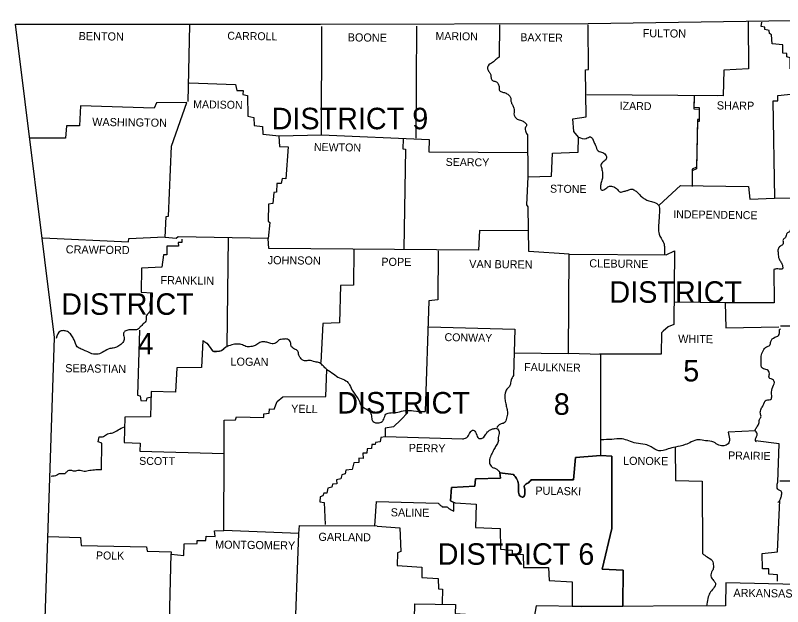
# Model space of a CAD drawing. Extents: x 1096785 to 1382432, y 216169 to 341661.
# Drawn here: x 1206233 to 1214365, y 286518 to 292788 of the extents above; entities that cross this region are included whole.
import ezdxf

# ---------------------------------------------------------------- set-up
doc = ezdxf.new("R2010")
doc.units = 0
for name, color, linetype in [('1', 7, 'Continuous'), ('21', 7, 'Continuous'), ('3', 7, 'Continuous')]:
    doc.layers.add(name, color=color, linetype=linetype)

msp = doc.modelspace()

# ---------------------------------------------------------------- linework, layer by layer
at = {"layer": '1'}
for p, q in [((1214341.4, 289493.9), (1214579.4, 289493.9)), ((1210893.4, 287619.9), (1210879.4, 287621.9)), ((1210879.4, 287621.9), (1210893.4, 287619.9)), ((1210067.4, 287371.9), (1210043.4, 287375.9)), ((1210757.4, 286553.9), (1210757.2, 286543.8)), ((1212133.4, 286521.9), (1212133.4, 286521.5)), ((1212133.4, 286521.9), (1212133.4, 286521.5)), ((1212133.4, 286521.5), (1212229.4, 286519.9)), ((1212229.4, 286519.9), (1212671.4, 286521.6)), ((1212671.4, 286535.9), (1212671.4, 286521.6)), ((1212671.4, 286521.6), (1212671.4, 286535.9))]:
    msp.add_line(p, q, dxfattribs=at)
for points in [[(1206233.4, 292695.9), (1209467.4, 292693.9), (1212305.4, 292699.9), (1215653.4, 292751.9), (1217205.4, 292787.9)], [(1206467.4, 283945.9), (1206647.4, 289371.9), (1206233.4, 292695.9)], [(1208079.4, 292683.9), (1208061.4, 291873.9)], [(1208075.4, 292071.9), (1208567.4, 292055.9), (1208579.4, 291991.9), (1208647.4, 291989.9), (1208645.4, 291949.9), (1208693.4, 291937.9), (1208697.4, 291719.9), (1208759.4, 291705.9), (1208763.4, 291619.9), (1208851.4, 291607.9), (1208855.4, 291527.9), (1209029.4, 291509.9), (1209477.4, 291519.9), (1209481.4, 292669.9)], [(1210483.4, 292673.9), (1210477.4, 291485.9)], [(1211363.4, 292687.9), (1211359.4, 292345.9)], [(1211699.4, 287861.9), (1212149.4, 287863.9), (1212169.4, 288099.9), (1212437.4, 288119.9), (1212437.4, 289191.9), (1212097.4, 289201.9), (1212103.4, 290255.9), (1211675.4, 290283.9), (1211669.4, 290755.9), (1211655.4, 290779.9), (1211667.4, 291075.9), (1211915.4, 291083.9), (1211925.4, 291327.9), (1212197.4, 291337.9), (1212201.4, 291495.9), (1212153.4, 291557.9), (1212141.4, 291691.9), (1212281.4, 291711.9), (1212275.4, 292209.9), (1212309.4, 292211.9), (1212305.4, 292687.9)], [(1213999.4, 292717.9), (1214003.4, 292221.9), (1213743.4, 292207.9), (1213735.4, 291935.9), (1212289.4, 291943.9)], [(1214565.4, 289481.9), (1214575.4, 289211.9), (1215101.4, 289225.9), (1215087.4, 290829.9), (1214281.4, 290847.9), (1214263.4, 291879.9), (1214315.4, 291881.9), (1214313.4, 291937.9), (1214483.4, 291953.9), (1214475.4, 292215.9), (1214443.4, 292221.9), (1214445.4, 292337.9), (1214409.4, 292347.9), (1214409.4, 292381.9), (1214367.4, 292387.9), (1214367.4, 292473.9), (1214253.4, 292485.9), (1214247.4, 292581.9), (1214225.4, 292595.9), (1214221.4, 292627.9), (1214175.4, 292637.9), (1214177.4, 292661.9), (1214137.4, 292667.9), (1214143.4, 292715.9)], [(1208921.4, 290315.9), (1208911.4, 290421.9), (1207957.4, 290439.9), (1207939.4, 290421.9), (1207821.4, 290431.9), (1207833.4, 290655.9), (1207857.4, 290657.9), (1207889.4, 291399.9), (1208051.4, 291863.9), (1207729.4, 291861.9), (1207705.4, 291801.9), (1206925.4, 291829.9), (1206913.4, 291615.9), (1206775.4, 291615.9), (1206765.4, 291483.9), (1206391.4, 291485.9)], [(1213427.4, 291929.9), (1213423.4, 291813.9), (1213479.4, 291809.9), (1213481.4, 291681.9), (1213461.4, 291681.9), (1213453.4, 291177.9), (1213407.4, 291157.9), (1213407.4, 290989.9)], [(1213427.4, 291911.9), (1213423.4, 291795.9), (1213479.4, 291791.9), (1213481.4, 291663.9), (1213461.4, 291663.9), (1213453.4, 291159.9), (1213407.4, 291139.9), (1213407.4, 290971.9)], [(1213677.4, 291925.9), (1213679.4, 291927.9)], [(1209025.4, 291505.9), (1209033.4, 291397.9), (1209125.4, 291391.9), (1209101.4, 291055.9), (1209059.4, 291057.9), (1209051.4, 291003.9), (1209003.4, 291003.9), (1209001.4, 290911.9), (1208971.4, 290909.9), (1208961.4, 290791.9), (1208917.4, 290785.9), (1208911.4, 290605.9), (1208931.4, 290591.9), (1208911.4, 290421.9)], [(1209477.4, 291519.9), (1210617.4, 291471.9), (1210615.4, 291341.9), (1211661.4, 291333.9)], [(1210343.4, 291477.9), (1210341.4, 291373.9), (1210367.4, 291367.9), (1210351.4, 290311.9)], [(1211667.4, 291075.9), (1211665.4, 291525.9)], [(1213055.4, 290775.9), (1213283.4, 290981.9), (1214003.4, 290971.9), (1214017.4, 290837.9), (1214279.4, 290847.9)], [(1211667.4, 290501.9), (1211151.4, 290507.9), (1211141.4, 290297.9), (1208921.4, 290315.9)], [(1206523.4, 290429.9), (1207433.4, 290387.9), (1207437.4, 290419.9), (1207817.4, 290437.9)], [(1207997.4, 290413.9), (1207997.4, 290377.9), (1207959.4, 290377.9), (1207961.4, 290341.9), (1207839.4, 290339.9), (1207837.4, 290249.9), (1207803.4, 290249.9), (1207785.4, 290115.9), (1207569.4, 290105.9), (1207567.4, 289851.9), (1207683.4, 289843.9)], [(1208219.4, 289339.9), (1208263.4, 289311.9), (1208327.4, 289227.9), (1208377.4, 289225.9), (1208417.4, 289233.9), (1208463.4, 289273.9), (1208477.4, 289275.9), (1208491.4, 290429.9)], [(1208477.4, 289275.9), (1208491.4, 290429.9)], [(1209819.4, 290299.9), (1209817.4, 289925.9), (1209679.4, 289923.9), (1209667.4, 289525.9), (1209491.4, 289519.9), (1209471.4, 289107.9)], [(1210715.4, 290289.9), (1210711.4, 289769.9), (1210615.4, 289761.9), (1210577.4, 288585.9)], [(1212103.4, 290255.9), (1213131.4, 290249.9), (1213219.4, 290291.9), (1213213.4, 289509.9), (1213153.4, 289483.9), (1213099.4, 289437.9), (1213081.4, 289419.9), (1213079.4, 289195.9), (1212425.4, 289195.9)], [(1214271.4, 290091.9), (1214275.4, 289739.9), (1213755.4, 289737.9), (1213221.4, 289747.9)], [(1213755.4, 289737.9), (1213763.4, 289475.9), (1214325.4, 289485.9)], [(1207547.4, 289447.9), (1207527.4, 288759.9), (1207557.4, 288751.9), (1207563.4, 288703.9), (1207623.4, 288699.9), (1207629.4, 288733.9), (1207677.4, 288741.9)], [(1210611.4, 289483.9), (1211525.4, 289461.9), (1211513.4, 288967.9)], [(1214341.4, 289459.9), (1214331.4, 289457.9)], [(1208219.4, 289339.9), (1208205.4, 289053.9), (1207945.4, 289051.9), (1207931.4, 288791.9), (1207673.4, 288797.9), (1207665.4, 288529.9), (1207395.4, 288527.9), (1207387.4, 288259.9), (1207557.4, 288249.9), (1207551.4, 288167.9), (1208446.2, 288143.1)], [(1211515.4, 289209.9), (1212097.4, 289201.9)], [(1215101.4, 289225.9), (1215131.4, 288129.9), (1214655.4, 288127.9), (1214653.4, 288083.9), (1214515.4, 288075.9), (1214503.4, 287847.9), (1214335.4, 287847.9)], [(1208446.2, 288143.1), (1208447.4, 288493.9), (1208567.4, 288497.9), (1208577.4, 288529.9), (1208867.4, 288521.9), (1208865.4, 288563.9), (1208923.4, 288569.9), (1208925.4, 288615.9), (1208975.4, 288611.9), (1209009.4, 288691.9), (1209069.4, 288743.9), (1209525.4, 288745.9), (1209533.4, 289033.9)], [(1210391.4, 288577.9), (1210319.4, 288499.9), (1210241.4, 288425.9), (1210151.4, 288411.9), (1210151.4, 288317.9), (1210107.4, 288311.9), (1210099.4, 288263.9), (1210049.4, 288259.9), (1210045.4, 288237.9), (1210011.4, 288235.9), (1210009.4, 288193.9), (1209961.4, 288191.9), (1209957.4, 288143.9), (1209917.4, 288143.9), (1209919.4, 288087.9), (1209875.4, 288091.9), (1209873.4, 288047.9), (1209819.4, 288043.9), (1209803.4, 287971.9), (1209735.4, 287965.9), (1209729.4, 287925.9), (1209693.4, 287915.9), (1209683.4, 287873.9), (1209637.4, 287863.9), (1209641.4, 287821.9), (1209595.4, 287817.9), (1209587.4, 287785.9), (1209545.4, 287773.9), (1209535.4, 287719.9), (1209503.4, 287721.9), (1209493.4, 287693.9), (1209463.4, 287683.9), (1209461.4, 287629.9), (1209507.4, 287621.9), (1209515.4, 287389.9)], [(1214077.4, 288381.9), (1213787.4, 288367.9)], [(1207145.4, 287969.9), (1207151.4, 288251.9), (1207111.4, 288263.9), (1207123.4, 288317.9)], [(1210977.4, 288293.9), (1210153.4, 288319.9)], [(1214313.4, 287837.9), (1214327.4, 288245.9), (1214077.4, 288277.9)], [(1213227.4, 288211.9), (1213231.4, 287853.9), (1213513.4, 287847.9), (1213515.4, 287079.9)], [(1206553.4, 285611.9), (1207099.4, 285587.9), (1207101.4, 285843.9), (1207073.4, 285863.9), (1207091.4, 286091.9), (1207861.4, 286089.9), (1207883.4, 287073.9), (1208019.4, 287061.9), (1208021.4, 287183.9), (1208161.4, 287187.9), (1208159.4, 287219.9), (1208253.4, 287219.9), (1208255.4, 287263.9), (1208351.4, 287261.9), (1208343.4, 287321.9), (1208443.4, 287323.9), (1208446.2, 288143.1)], [(1212437.4, 288119.9), (1212169.4, 288099.9), (1212149.4, 287863.9), (1211699.4, 287861.9)], [(1212437.4, 288119.9), (1212553.4, 288111.9), (1212555.4, 287347.9), (1212451.4, 286913.9), (1212673.4, 286903.9), (1212671.4, 286535.9)], [(1212671.4, 286535.9), (1212673.4, 286903.9), (1212451.4, 286913.9), (1212555.4, 287347.9), (1212553.4, 288111.9), (1212437.4, 288119.9)], [(1210879.4, 287529.9), (1210879.4, 287621.9), (1210843.4, 287639.9), (1210857.4, 287779.9), (1211103.4, 287793.9), (1211111.4, 287871.9), (1211373.4, 287881.9), (1211367.4, 287935.9), (1211511.4, 287919.9)], [(1211511.4, 287919.9), (1211367.4, 287935.9), (1211373.4, 287881.9), (1211111.4, 287871.9), (1211103.4, 287793.9), (1210857.4, 287779.9), (1210843.4, 287639.9), (1210879.4, 287621.9)], [(1212139.4, 287865.9), (1212149.4, 287875.9)], [(1209239.4, 287293.9), (1209243.4, 287379.9), (1210043.4, 287375.9), (1210061.4, 287633.9), (1210715.4, 287613.9)], [(1214311.4, 286787.9), (1214309.4, 286853.9), (1214219.4, 286863.9), (1214217.4, 286919.9), (1214151.4, 286917.9), (1214147.4, 287079.9), (1214311.4, 287097.9), (1214335.4, 287645.9)], [(1210893.4, 287619.9), (1211117.4, 287605.9), (1211109.4, 287355.9), (1211371.4, 287345.9), (1211375.4, 287127.9), (1211499.4, 287117.9), (1211499.4, 287079.9), (1211615.4, 287071.9), (1211619.4, 286931.9), (1211883.4, 286931.9), (1211891.4, 286793.9), (1212135.4, 286781.9), (1212133.4, 286521.9)], [(1210893.4, 287619.9), (1211117.4, 287605.9), (1211109.4, 287355.9), (1211371.4, 287345.9), (1211375.4, 287127.9), (1211499.4, 287117.9), (1211499.4, 287079.9), (1211615.4, 287071.9), (1211619.4, 286931.9), (1211883.4, 286931.9), (1211891.4, 286793.9), (1212135.4, 286781.9), (1212133.4, 286521.9)], [(1210067.4, 287371.9), (1210309.4, 287353.9), (1210317.4, 287101.9), (1210283.4, 287089.9), (1210279.4, 286955.9), (1210541.4, 286937.9), (1210541.4, 286827.9), (1210715.4, 286817.9), (1210717.4, 286707.9), (1210759.4, 286701.9), (1210757.4, 286553.9)], [(1206577.4, 287261.9), (1206923.4, 287249.9), (1206931.4, 287165.9), (1207623.4, 287151.9), (1207631.4, 287107.9), (1207883.4, 287099.9), (1207881.4, 287061.9)], [(1209193.4, 286047.9), (1209239.4, 287293.9)], [(1214519.4, 286751.9), (1213763.4, 286771.9), (1213759.4, 286525.9), (1212229.4, 286519.9)], [(1209207.4, 286213.9), (1210351.4, 286197.9), (1210373.4, 286387.9), (1210463.4, 286387.9), (1210465.4, 286547.9), (1210897.4, 286541.9), (1210893.4, 286445.9), (1211005.4, 286437.9), (1211005.4, 286261.9), (1211077.4, 286255.9)], [(1212229.4, 286519.9), (1211751.4, 286527.9), (1211733.4, 286405.9), (1211267.4, 286391.9), (1211263.4, 286351.9), (1211197.4, 286339.9), (1211189.4, 286271.9), (1211077.4, 286255.9)]]:
    msp.add_lwpolyline(points, dxfattribs=at)
for points in [[(1211359.4, 292345.9), (1211323.4, 292315.9), (1211291.4, 292287.9), (1211243.4, 292253.9), (1211237.4, 292221.9), (1211253.4, 292189.9), (1211269.4, 292163.9), (1211275.4, 292127.9), (1211289.4, 292097.9), (1211323.4, 292085.9), (1211351.4, 292059.9), (1211361.4, 292023.9), (1211365.4, 291989.9), (1211397.4, 291973.9), (1211433.4, 291961.9), (1211467.4, 291937.9), (1211483.4, 291907.9), (1211487.4, 291869.9), (1211501.4, 291839.9), (1211517.4, 291803.9), (1211521.4, 291773.9), (1211517.4, 291743.9), (1211525.4, 291715.9), (1211551.4, 291687.9), (1211597.4, 291673.9), (1211629.4, 291653.9), (1211651.4, 291625.9), (1211637.4, 291591.9), (1211639.4, 291561.9), (1211657.4, 291525.9)], [(1212201.4, 291495.9), (1212281.4, 291481.9), (1212329.4, 291499.9), (1212363.4, 291447.9), (1212381.4, 291407.9), (1212411.4, 291349.9), (1212459.4, 291331.9), (1212495.4, 291299.9), (1212495.4, 291265.9), (1212463.4, 291233.9), (1212439.4, 291201.9), (1212447.4, 291163.9), (1212455.4, 291111.9), (1212455.4, 291061.9), (1212443.4, 291015.9), (1212433.4, 290973.9), (1212443.4, 290937.9), (1212481.4, 290943.9), (1212521.4, 290973.9), (1212563.4, 290973.9), (1212603.4, 290951.9), (1212645.4, 290913.9), (1212687.4, 290921.9), (1212721.4, 290931.9), (1212769.4, 290945.9), (1212803.4, 290927.9), (1212833.4, 290903.9), (1212869.4, 290865.9), (1212903.4, 290841.9), (1212947.4, 290819.9), (1213001.4, 290805.9), (1213051.4, 290771.9), (1213059.4, 290713.9), (1213057.4, 290663.9), (1213053.4, 290601.9), (1213049.4, 290533.9), (1213055.4, 290467.9), (1213077.4, 290423.9), (1213105.4, 290371.9), (1213113.4, 290323.9), (1213111.4, 290247.9)], [(1214629.4, 290811.9), (1214605.4, 290749.9), (1214577.4, 290689.9), (1214559.4, 290637.9), (1214521.4, 290607.9), (1214509.4, 290579.9), (1214475.4, 290567.9), (1214449.4, 290527.9), (1214437.4, 290491.9), (1214409.4, 290475.9), (1214395.4, 290431.9), (1214369.4, 290407.9), (1214371.4, 290367.9), (1214341.4, 290339.9), (1214317.4, 290307.9), (1214317.4, 290263.9), (1214327.4, 290205.9), (1214347.4, 290171.9), (1214365.4, 290127.9), (1214363.4, 290099.9), (1214313.4, 290099.9), (1214271.4, 290091.9)], [(1207683.4, 289843.9), (1207683.4, 289801.9), (1207667.4, 289757.9), (1207657.4, 289719.9), (1207663.4, 289669.9), (1207645.4, 289629.9), (1207619.4, 289597.9), (1207619.4, 289557.9), (1207589.4, 289515.9), (1207557.4, 289483.9), (1207529.4, 289457.9), (1207479.4, 289453.9), (1207437.4, 289451.9), (1207395.4, 289437.9), (1207379.4, 289407.9), (1207387.4, 289361.9), (1207371.4, 289317.9), (1207329.4, 289283.9), (1207283.4, 289261.9), (1207235.4, 289253.9), (1207169.4, 289221.9), (1207109.4, 289195.9), (1207045.4, 289199.9), (1206985.4, 289225.9), (1206931.4, 289249.9), (1206889.4, 289273.9), (1206855.4, 289347.9), (1206833.4, 289387.9), (1206795.4, 289427.9), (1206749.4, 289443.9), (1206711.4, 289439.9), (1206665.4, 289361.9)], [(1214087.4, 288263.9), (1214077.4, 288277.9), (1214089.4, 288321.9), (1214095.4, 288349.9), (1214075.4, 288389.9), (1214093.4, 288423.9), (1214113.4, 288459.9), (1214119.4, 288501.9), (1214135.4, 288529.9), (1214129.4, 288565.9), (1214137.4, 288615.9), (1214159.4, 288653.9), (1214191.4, 288707.9), (1214245.4, 288721.9), (1214249.4, 288743.9), (1214247.4, 288793.9), (1214269.4, 288867.9), (1214277.4, 288893.9), (1214269.4, 288917.9), (1214221.4, 288945.9), (1214225.4, 288987.9), (1214201.4, 289027.9), (1214151.4, 289045.9), (1214137.4, 289113.9), (1214137.4, 289173.9), (1214159.4, 289231.9), (1214193.4, 289273.9), (1214229.4, 289289.9), (1214239.4, 289329.9), (1214283.4, 289373.9), (1214321.4, 289391.9), (1214331.4, 289457.9)], [(1208219.4, 289339.9), (1208263.4, 289311.9), (1208297.4, 289265.9), (1208327.4, 289227.9), (1208377.4, 289225.9), (1208417.4, 289233.9), (1208463.4, 289273.9)], [(1209533.4, 289033.9), (1209495.4, 289069.9), (1209455.4, 289103.9), (1209411.4, 289113.9), (1209343.4, 289127.9), (1209299.4, 289123.9), (1209273.4, 289135.9), (1209255.4, 289155.9), (1209237.4, 289185.9), (1209227.4, 289227.9), (1209193.4, 289249.9), (1209155.4, 289283.9), (1209149.4, 289319.9), (1209119.4, 289353.9), (1209077.4, 289353.9), (1209029.4, 289345.9), (1209001.4, 289319.9), (1208953.4, 289305.9), (1208909.4, 289317.9), (1208867.4, 289325.9), (1208823.4, 289317.9), (1208783.4, 289291.9), (1208743.4, 289277.9), (1208689.4, 289273.9), (1208639.4, 289293.9), (1208591.4, 289301.9), (1208543.4, 289297.9), (1208477.4, 289275.9)], [(1209533.4, 289033.9), (1209603.4, 288985.9), (1209669.4, 288943.9), (1209737.4, 288913.9), (1209775.4, 288869.9), (1209809.4, 288801.9), (1209837.4, 288759.9), (1209873.4, 288707.9), (1209899.4, 288649.9), (1209941.4, 288617.9), (1209985.4, 288589.9), (1210007.4, 288539.9), (1210017.4, 288489.9), (1210065.4, 288465.9), (1210111.4, 288475.9), (1210137.4, 288505.9), (1210161.4, 288557.9), (1210215.4, 288573.9), (1210285.4, 288579.9), (1210365.4, 288597.9), (1210453.4, 288593.9), (1210577.4, 288585.9)], [(1211513.4, 288967.9), (1211487.4, 288921.9), (1211475.4, 288861.9), (1211443.4, 288823.9), (1211423.4, 288779.9), (1211421.4, 288721.9), (1211431.4, 288669.9), (1211441.4, 288619.9), (1211449.4, 288573.9), (1211439.4, 288515.9), (1211413.4, 288465.9), (1211373.4, 288451.9), (1211335.4, 288417.9)], [(1207123.4, 288317.9), (1207167.4, 288321.9), (1207209.4, 288349.9), (1207265.4, 288361.9), (1207321.4, 288391.9), (1207391.4, 288423.9)], [(1210977.4, 288293.9), (1211027.4, 288321.9), (1211053.4, 288363.9), (1211085.4, 288389.9), (1211117.4, 288353.9), (1211145.4, 288301.9), (1211175.4, 288301.9), (1211213.4, 288337.9), (1211237.4, 288369.9), (1211267.4, 288393.9), (1211299.4, 288403.9), (1211333.4, 288407.9), (1211359.4, 288369.9), (1211351.4, 288309.9), (1211351.4, 288269.9), (1211329.4, 288227.9), (1211305.4, 288183.9), (1211279.4, 288133.9), (1211259.4, 288079.9), (1211263.4, 288027.9), (1211291.4, 287993.9), (1211323.4, 287983.9), (1211367.4, 287939.9)], [(1213787.4, 288367.9), (1213787.4, 288243.9), (1213689.4, 288229.9), (1213635.4, 288261.9), (1213549.4, 288277.9), (1213473.4, 288287.9), (1213397.4, 288263.9), (1213331.4, 288235.9), (1213229.4, 288209.9), (1213151.4, 288189.9), (1213051.4, 288171.9), (1212973.4, 288211.9), (1212907.4, 288237.9), (1212813.4, 288249.9), (1212733.4, 288275.9), (1212663.4, 288295.9), (1212553.4, 288291.9), (1212441.4, 288287.9)], [(1207145.4, 287969.9), (1207087.4, 287967.9), (1207021.4, 287959.9), (1206961.4, 287951.9), (1206907.4, 287961.9), (1206857.4, 287953.9), (1206823.4, 287961.9), (1206781.4, 287951.9), (1206757.4, 287927.9), (1206707.4, 287927.9), (1206671.4, 287911.9), (1206613.4, 287897.9)], [(1211511.4, 287919.9), (1211545.4, 287875.9), (1211565.4, 287815.9), (1211565.4, 287747.9), (1211581.4, 287691.9), (1211613.4, 287679.9), (1211633.4, 287727.9), (1211629.4, 287775.9), (1211629.4, 287803.9), (1211663.4, 287827.9), (1211699.4, 287861.9)], [(1211699.4, 287861.9), (1211663.4, 287827.9), (1211629.4, 287803.9), (1211629.4, 287775.9), (1211633.4, 287727.9), (1211613.4, 287679.9), (1211581.4, 287691.9), (1211565.4, 287747.9), (1211565.4, 287815.9), (1211545.4, 287875.9), (1211511.4, 287919.9)], [(1214317.4, 287621.9), (1214335.4, 287645.9), (1214343.4, 287661.9), (1214353.4, 287701.9), (1214349.4, 287741.9), (1214321.4, 287755.9), (1214305.4, 287797.9), (1214313.4, 287837.9)], [(1210715.4, 287613.9), (1210739.4, 287591.9), (1210765.4, 287575.9), (1210797.4, 287577.9), (1210827.4, 287559.9), (1210879.4, 287529.9)], [(1213515.4, 287079.9), (1213565.4, 287045.9), (1213617.4, 287005.9), (1213631.4, 286951.9), (1213627.4, 286913.9), (1213611.4, 286881.9), (1213607.4, 286831.9), (1213631.4, 286795.9), (1213653.4, 286765.9), (1213631.4, 286711.9), (1213593.4, 286661.9), (1213573.4, 286605.9), (1213559.4, 286521.9)]]:
    msp.add_spline(points, degree=3, dxfattribs=at)
at = {"layer": '21'}
msp.add_lwpolyline([(1209239.4, 287293.9), (1208443.4, 287323.9)], dxfattribs=at)

# ---------------------------------------------------------------- texts
for s, p in [('DISTRICT 9', (1208949.4, 291579.9)), ('DISTRICT', (1212529.4, 289739.9)), ('DISTRICT', (1206718.9, 289612.3)), ('4', (1207528.9, 289192.3)), ('5', (1213311.4, 288905.9)), ('DISTRICT', (1209645.4, 288565.9)), ('8', (1211939.4, 288551.9)), ('DISTRICT 6', (1210709.4, 286961.9))]:
    msp.add_text(s, height=228, dxfattribs=at).set_placement(p)
at = {"layer": '3'}
for s, height, rotation, p in [('BENTON', 86.02, 359.25271, (1206903.4, 292525.9)), ('CARROLL', 84.01, 359.14808, (1208479.4, 292529.9)), ('BOONE', 86.02, 359.40007, (1209755.4, 292511.9)), ('MARION', 84.01, 359.18542, (1210685.4, 292527.9)), ('BAXTER', 84.01, 359.25594, (1211585.4, 292513.9)), ('FULTON', 85.99, 359.49961, (1212881.4, 292555.9)), ('MADISON', 84.01, 359.09062, (1208117.4, 291803.9)), ('IZARD', 83.99, 358.92583, (1212637.4, 291787.9)), ('SHARP', 85.99, 359.39049, (1213667.4, 291789.9)), ('WASHINGTON', 85.99, 359.23201, (1207047.4, 291615.9)), ('NEWTON', 84.01, 359.2717, (1209397.4, 291349.9)), ('SEARCY', 83.99, 359.25271, (1210793.4, 291191.9)), ('STONE', 83.99, 359.40007, (1211899.4, 290907.9)), ('INDEPENDENCE', 83.988, 359.21874, (1213205.4, 290637.9)), ('CRAWFORD', 85.99, 359.27706, (1206767.4, 290263.9)), ('JOHNSON', 86.02, 359.3514, (1208907.4, 290149.9)), ('POPE', 86.02, 359.61547, (1210111.4, 290131.9)), ('VAN BUREN', 86.02, 359.35078, (1211043.4, 290109.9)), ('CLEBURNE', 85.99, 359.25352, (1212315.4, 290115.9)), ('FRANKLIN', 86.02, 359.18154, (1207771.4, 289937.9)), ('CONWAY', 83.99, 359.03714, (1210781.4, 289333.9)), ('WHITE', 86.02, 359.31386, (1213257.4, 289315.9)), ('LOGAN', 86.02, 359.39691, (1208513.4, 289073.9)), ('FAULKNER', 84.01, 359.24862, (1211625.4, 289017.9)), ('SEBASTIAN', 85.99, 359.28159, (1206761.4, 289003.9)), ('YELL', 86.02, 359.19871, (1209155.4, 288573.9)), ('PERRY', 84.01, 359.08578, (1210403.4, 288159.9)), ('PRAIRIE', 84.01, 359.21158, (1213787.4, 288079.9)), ('SCOTT', 84.01, 359.40628, (1207545.4, 288021.9)), ('LONOKE', 86.02, 359.49742, (1212673.4, 288021.9)), ('PULASKI', 86.02, 359.05305, (1211743.4, 287705.9)), ('SALINE', 86.02, 359.14914, (1210211.4, 287475.9)), ('GARLAND', 86.02, 359.36576, (1209445.4, 287215.9)), ('MONTGOMERY', 86.02, 359.29442, (1208349.4, 287133.9)), ('POLK', 83.99, 359.21517, (1207087.4, 287019.9)), ('ARKANSAS', 85.99, 359.26783, (1213843.4, 286621.9))]:
    msp.add_text(s, height=height, rotation=rotation, dxfattribs=at).set_placement(p)

doc.saveas('drawing.dxf')
